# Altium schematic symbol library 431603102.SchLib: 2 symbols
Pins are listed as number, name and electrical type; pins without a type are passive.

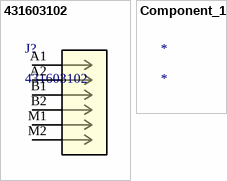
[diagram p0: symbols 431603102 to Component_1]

## 431603102
designator J?
No Description Available; Mfr_Name: Molex Connector Corporation
footprint CON_431603102_MOL
pins: A1, A2, B1, B2, M1, M2

## Component_1
designator *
